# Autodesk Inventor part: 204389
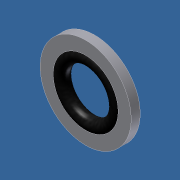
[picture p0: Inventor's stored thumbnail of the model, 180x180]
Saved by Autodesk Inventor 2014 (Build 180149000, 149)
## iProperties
Shininess: 20.0
Length Units: 11272
Angle Units: 11279
Time Units: 11290
Mass Units: 11286
Length Display Precision: 3
Angle Display Precision: 2
Company: Autodesk, Inc.
Created: 2002-07
Part Number: 204389
Material: Steel, Mild
Description: SEAL; STATO 600-0101-3/8
Document SubType Name: Modeling
Designer: Autodesk, Inc.
Density: 7.86 g/cm^3
Mass: 1.95946 g
Surface Area: 4.36827 cm^2
Volume: 0.249295 cm^3
Appearance: Steel
Density: 0.0
Volumn: 0.0
Area: 0.0
PropertySet Name: Model Information
Control State: 0
Master: False
Checked Out: False
Last Check In By: JT
Last Check In Date: 2003-06-20
Title: SEAL; STATO 600-0101-3/8
Author: Autodesk, Inc.
Comments: -
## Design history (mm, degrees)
derived "STATO.ipt"
body "Solid1"
tag "TaggingFeature2"
feature "Solid1::STATO.ipt" dims "ScaleForDerivedMember" = 10
